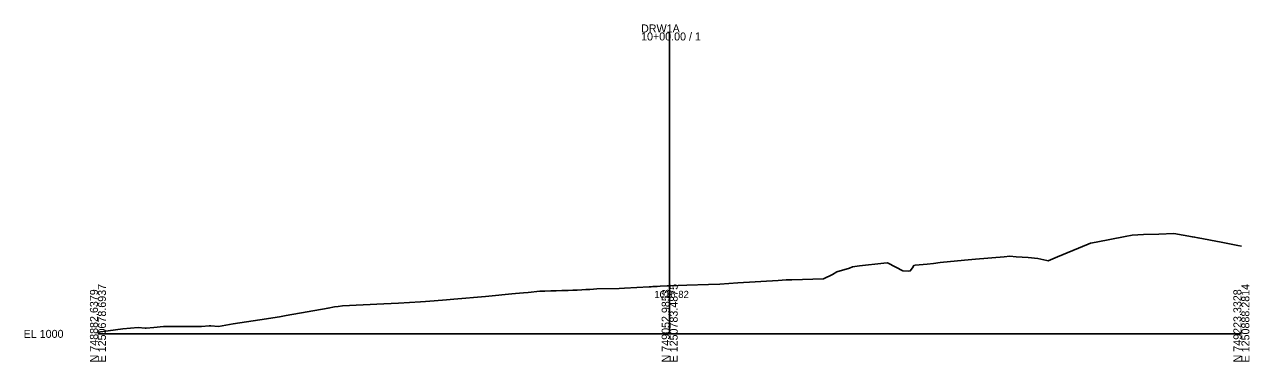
# Model space of a CAD drawing. Extents: x -26 to 403, y -376 to 1112.
# Drawn here: x -25.7 to 402.8, y -9.7 to 108.4 of the extents above; entities that cross this region are included whole.
import ezdxf

# ---------------------------------------------------------------- set-up
doc = ezdxf.new("R2010")
doc.units = 0
for name, color, linetype in [('Exist Cross Section Cell', 7, 'Continuous'), ('Exist XS Center Line Elevation Label', 7, 'Continuous'), ('Exist XS Ground Line', 7, 'Continuous')]:
    doc.layers.add(name, color=color, linetype=linetype)

msp = doc.modelspace()

# ---------------------------------------------------------------- linework, layer by layer
at = {"layer": 'Exist Cross Section Cell'}
for p, q in [((200, 0), (200, 105.57)), ((0, 0), (200, 0)), ((200, 0), (400, 0))]:
    msp.add_line(p, q, dxfattribs=at)
at = {"layer": 'Exist XS Ground Line'}
msp.add_lwpolyline([(0, 0.55), (3.52, 1.02), (8.68, 1.72), (14.03, 2.27), (16.55, 2.02), (16.9, 2), (19.55, 2.23), (22.96, 2.55), (25.97, 2.57), (28.56, 2.57), (32.92, 2.59), (36.26, 2.58), (38.95, 2.81), (39.51, 2.86), (42.17, 2.63), (47.25, 3.5), (56.6, 4.86), (63.53, 5.99), (65.84, 6.42), (80.53, 9.05), (82.7, 9.42), (84.06, 9.64), (85.54, 9.84), (99.99, 10.52), (105.09, 10.78), (112.81, 11.19), (114.64, 11.31), (117.63, 11.57), (121.91, 11.91), (124.55, 12.11), (135.61, 13.09), (136.72, 13.2), (144.8, 14.03), (146.05, 14.13), (147.43, 14.22), (148.92, 14.33), (150.53, 14.43), (154.64, 14.9), (156.33, 14.98), (158.48, 15.09), (160.25, 15.12), (162.23, 15.17), (163.85, 15.21), (164.47, 15.22), (166.09, 15.27), (167.68, 15.34), (169.22, 15.4), (170.7, 15.48), (172.08, 15.56), (173.36, 15.64), (174.52, 15.73), (182.39, 15.86), (184.16, 15.96), (192.78, 16.46), (193.5, 16.5), (194.11, 16.54), (194.63, 16.57), (195.07, 16.6), (195.58, 16.63), (196.65, 16.69), (199.17, 16.79), (200, 16.82), (205.99, 17.01), (213.6, 17.26), (217.51, 17.42), (223.89, 17.82), (237.95, 18.74), (240.72, 18.91), (242.69, 18.97), (253.87, 19.28), (256.95, 20.78), (258.51, 21.69), (262.86, 23.05), (263.97, 23.46), (266.46, 23.84), (274.96, 24.79), (276.1, 24.92), (276.47, 24.71), (281.55, 22.1), (283.5, 22.01), (284.16, 22.03), (284.9, 23.09), (285.45, 23.97), (285.94, 24.03), (290.12, 24.39), (292.34, 24.68), (294.68, 24.98), (303.14, 25.81), (307.03, 26.17), (317, 27.03), (319, 27.2), (321.25, 27.03), (325.46, 26.69), (328.82, 26.37), (331.96, 25.64), (332.38, 25.59), (335.69, 26.94), (346.39, 31.38), (347.23, 31.74), (349.2, 32.1), (359.39, 34.08), (361.82, 34.53), (365.77, 34.83), (371.14, 34.94), (376.36, 35.19), (382.88, 33.98), (383.63, 33.89), (384.86, 33.63), (392.89, 32.09), (394.11, 31.84), (395.9, 31.5), (398.71, 30.96), (400, 30.69)], dxfattribs=at)

# ---------------------------------------------------------------- texts
at = {"layer": 'Exist Cross Section Cell'}
for s, p in [('DRW1A', (190, 105.57)), ('10+00.00 / 1', (190, 102.77)), ('EL 1000', (-26, -1.4))]:
    msp.add_text(s, height=2.8, dxfattribs=at).set_placement(p)
for s, p in [('E 1250678.6937', (2.8, -10)), ('E 1250783.4875', (202.8, -10)), ('E 1250888.2814', (402.8, -10)), ('N 748882.6379', (0, -10)), ('N 749052.9853', (200, -10)), ('N 749223.3328', (400, -10))]:
    msp.add_text(s, height=2.8, rotation=90, dxfattribs=at).set_placement(p)
at = {"layer": 'Exist XS Center Line Elevation Label'}
msp.add_text('1016.82', height=2.5, dxfattribs=at).set_placement((194.64, 12.57))

doc.saveas('drawing.dxf')
